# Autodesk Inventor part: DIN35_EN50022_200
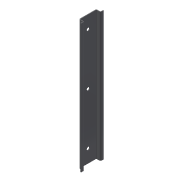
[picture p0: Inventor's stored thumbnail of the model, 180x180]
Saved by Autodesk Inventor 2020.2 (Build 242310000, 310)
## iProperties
Created: 2015-10
Part Number: DIN35_EN50022_200
Material: Stal
Document SubType Name: Konstrukcja blachowa
Designer: F.Stasiak
Density: 7.85 g/cm^3
Sheet Metal Rule: Blacha stalowa 1.0 mm/Spoina liniowa
Appearance: Stal
Description: Szyna DIN 200 mm
Catalog Web Link: www.expertbooks.pl
Manager: www.cadconsulting.pl
Company: Fabian Stasiak CAD Consulting
Author: F.Stasiak
Subject: Zbiór ćwiczeń. Autodesk Inventor 2020. Kurs Professional
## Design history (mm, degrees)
sketch "Szkic1"
  geometry: L1 (7.5, -16)-(7.497, -16); L2 (6.5, -17.5)-(7.5, -17.5); L3 (7.5, -14.3)-(7.5, -17.5); L4 (7.5, 17.5)-(6.5, 17.5); L5 (7.5, 14.3)-(7.5, 17.5); L6 (1, -12)-(1, 12); L7 (0, -11.7)-(0, 11.7); L8 (1.8, -13.5)-(6, -13.5); L9 (1.5, -12.5)-(5.7, -12.5); L10 (6.5, -14)-(6.5, -17.5); L11 (1.5, 12.5)-(5.7, 12.5); L12 (1.8, 13.5)-(6, 13.5); L13 (6.5, 14)-(6.5, 17.5); A1 r 0.5 centre (1.5, 12) between (1.5, 12.5) and (1, 12); A2 r 0.5 centre (6, -14) between (6.5, -14) and (6, -13.5); A3 r 0.5 centre (6, 14) between (6, 13.5) and (6.5, 14); A4 r 1.8 centre (5.7, 14.3) between (5.7, 12.5) and (7.5, 14.3); A5 r 1.8 centre (1.8, 11.7) between (1.8, 13.5) and (0, 11.7); A6 r 1.8 centre (1.8, -11.7) between (0, -11.7) and (1.8, -13.5); A7 r 1.8 centre (5.7, -14.3) between (7.5, -14.3) and (5.7, -12.5); A8 r 0.5 centre (1.5, -12) between (1, -12) and (1.5, -12.5); 2 further points
  constraints: 26 end point, 16 point on circle, 8 centre point, 2 point on line, 1 midpoint
extrude "Wyciągnięcie proste1" new body sketch "Szkic1" distance "d0" = 200; taper "d1" = 0 deg
sketch "Szkic2"
  geometry: L1 (0, 0)-(0, 23.4) reference; L2 (200, 23.4)-(200, 0) reference; L3 (0, 23.4)-(200, 23.4) reference; 7 further points
  constraints: 3 midpoint, 2 horizontal alignment, 1 vertical alignment
  dimensions: "d2" = 20 distance from line of point (20, 11.7) L1; "d3" = 20 distance from line of point (180, 11.7) L2 (= d2)
hole "Otwór1" sketch "Szkic2" at (20, 11.7), (180, 11.7), (100, 11.7) diameter "d4" = 4.5; stored, may be unused: countersink angle "d8" = 90 deg, drill point angle "d10" = 118 deg; dims "d5" = 6, "d6" = 4, "d7" = 2, "d9" = 1 (= Grubość)
node "Bryła1"
other parameters: "Grubość" = 1 (derived), "WspółczynnikK" = 4.4, "PromieńGięcia" = 1 (= Grubość), "SzerokośćGięciaPodcięcia" = 1 (= Grubość), "GłębokośćGięciaPodcięcia" = 0.5 (= 0.5 x Grubość), "RozmiarPodcięciaNarożnika" = 4 (= 4 x Grubość), "OdstępPołączenia" = 0.01, "MinimalnaPozostałość" = 2 (= 2 x Grubość), "PromieńPrzejścia" = 1 (= PromieńGięcia), "Rozmiar_promienia_Jacobiego" = 1 (= PromieńGięcia), "Wielk_odstępu" = 1 (= Grubość)
